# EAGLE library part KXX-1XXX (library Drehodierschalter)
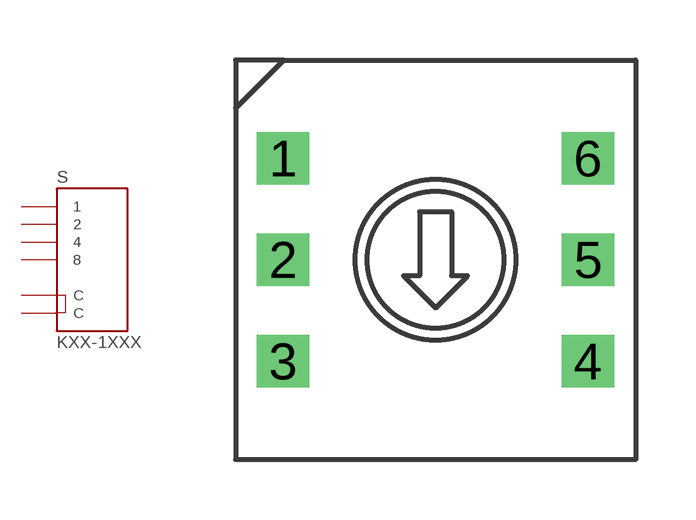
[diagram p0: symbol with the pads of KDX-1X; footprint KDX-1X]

Designator prefix S

## KXX-1XXX  [KDX-1X]
1  1
2  C  pwr
3  4
4  2
5  C  pwr
6  8

## Footprint KDX-1X (pad centres in mm)
drill 0.8 square: 1 -3.81,2.54; 2 -3.81,0; 3 -3.81,-2.54; 4 3.81,-2.54; 5 3.81,0; 6 3.81,2.54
